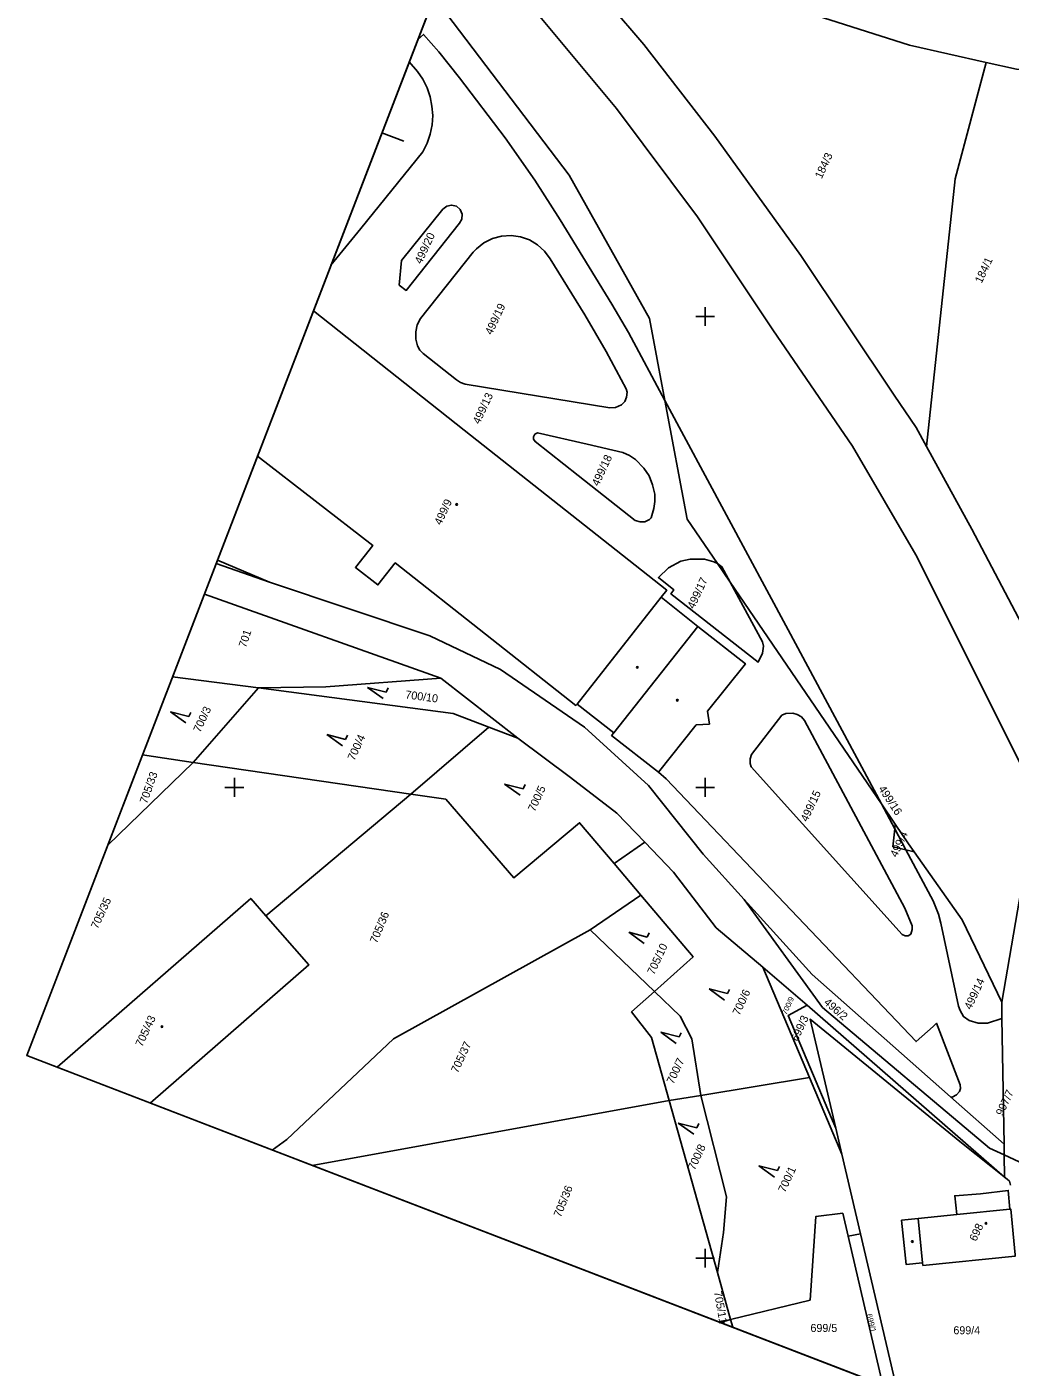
# Model space of a CAD drawing. Extents: x -755344 to -754412, y -1162670 to -1161477.
# Drawn here: x -755344.1 to -755135.2, y -1162523.1 to -1162238.5 of the extents above; entities that cross this region are included whole.
import ezdxf

# ---------------------------------------------------------------- set-up
doc = ezdxf.new("R2010")
doc.units = 0
for name, color, linetype in [('Formát', 7, 'Continuous'), ('Síť', 7, 'Continuous'), ('Vrstva 55', 7, 'Continuous'), ('Vrstva 56', 7, 'Continuous'), ('Vrstva 57', 7, 'Continuous'), ('Vrstva 58', 7, 'Continuous'), ('Vrstva 59', 7, 'Continuous')]:
    doc.layers.add(name, color=color, linetype=linetype)

msp = doc.modelspace()

# ---------------------------------------------------------------- linework, layer by layer
at = {"layer": 'Formát'}
for p, q in [((-755042.37, -1161673.02), (-755344.08, -1162456.97)), ((-755042.37, -1161673.02), (-755344.08, -1162456.97)), ((-755268.65, -1162260.99), (-755263.98, -1162262.78)), ((-755344.08, -1162456.97), (-754789.71, -1162670.32))]:
    msp.add_line(p, q, dxfattribs=at)
msp.add_lwpolyline([(-754488.01, -1161886.37), (-754789.71, -1162670.32), (-755344.08, -1162456.97), (-755042.37, -1161673.02)], close=True, dxfattribs=at)
for points in [[(-755344.08, -1162456.97), (-754789.71, -1162670.32), (-754488.01, -1161886.37), (-755042.37, -1161673.02)], [(-755344.08, -1162456.97), (-754789.71, -1162670.32), (-754488.01, -1161886.37), (-755042.37, -1161673.02)], [(-754789.71, -1162670.32), (-754488.01, -1161886.37), (-755042.37, -1161673.02), (-755344.08, -1162456.97)]]:
    msp.add_lwpolyline(points, dxfattribs=at)
at = {"layer": 'Síť'}
for points in [[(-755198, -1162300), (-755200, -1162300), (-755202, -1162300)], [(-755200, -1162298), (-755200, -1162300), (-755200, -1162302)], [(-755298, -1162400), (-755300, -1162400), (-755302, -1162400)], [(-755300, -1162398), (-755300, -1162400), (-755300, -1162402)], [(-755198, -1162400), (-755200, -1162400), (-755202, -1162400)], [(-755200, -1162398), (-755200, -1162400), (-755200, -1162402)], [(-755200, -1162498), (-755200, -1162500), (-755200, -1162502)], [(-755198, -1162500), (-755200, -1162500), (-755202, -1162500)]]:
    msp.add_lwpolyline(points, dxfattribs=at)
at = {"layer": 'Vrstva 55'}
for p, q in [((-755197.4, -1162352.43), (-755194.7, -1162356.4)), ((-755194.7, -1162356.4), (-755162.59, -1162403.5)), ((-755256.17, -1162376.79), (-755306.36, -1162358.97)), ((-755256.17, -1162376.79), (-755306.36, -1162358.97)), ((-755256.17, -1162376.79), (-755280.56, -1162378.65)), ((-755239.79, -1162389.54), (-755256.17, -1162376.79)), ((-755239.79, -1162389.54), (-755256.17, -1162376.79)), ((-755308.72, -1162394.69), (-755294.89, -1162378.88)), ((-755280.56, -1162378.65), (-755294.89, -1162378.88)), ((-755262.5, -1162401.42), (-755245.93, -1162387.2)), ((-755239.79, -1162389.54), (-755245.93, -1162387.2)), ((-755228.6, -1162397.87), (-755239.79, -1162389.54)), ((-755228.6, -1162397.87), (-755239.79, -1162389.54)), ((-755319.5, -1162393.12), (-755308.72, -1162394.69)), ((-755326.86, -1162412.25), (-755308.72, -1162394.69)), ((-755308.72, -1162394.69), (-755262.5, -1162401.42)), ((-755293.31, -1162427.26), (-755262.5, -1162401.42)), ((-755262.5, -1162401.42), (-755255.05, -1162402.51)), ((-755162.59, -1162403.5), (-755159.64, -1162407.83)), ((-755159.74, -1162408.83), (-755162.59, -1162403.5)), ((-755159.64, -1162407.83), (-755159.74, -1162408.83)), ((-755219.35, -1162416.19), (-755212.85, -1162411.61)), ((-755157.36, -1162413.27), (-755155.59, -1162413.71)), ((-755219.35, -1162416.19), (-755213.66, -1162422.91)), ((-755137.03, -1162445.6), (-755132.49, -1162419.21)), ((-755213.66, -1162422.91), (-755224.46, -1162430.27)), ((-755224.46, -1162430.27), (-755210.79, -1162443.34)), ((-755178.31, -1162446.22), (-755187.75, -1162438.21)), ((-755177.87, -1162461.62), (-755187.75, -1162438.21)), ((-755178.31, -1162446.22), (-755187.75, -1162438.21)), ((-755136.97, -1162449.09), (-755137.03, -1162445.6)), ((-755136.42, -1162482.75), (-755178.31, -1162446.22)), ((-755136.42, -1162482.75), (-755178.31, -1162446.22)), ((-755136.53, -1162475.81), (-755136.97, -1162449.09)), ((-755211.4, -1162453.1), (-755207.64, -1162466.53)), ((-755177.87, -1162461.62), (-755200.95, -1162465.43)), ((-755170.99, -1162477.93), (-755177.87, -1162461.62)), ((-755207.64, -1162466.53), (-755200.95, -1162465.43)), ((-755207.64, -1162466.53), (-755283.5, -1162480.29)), ((-755207.64, -1162466.53), (-755197.41, -1162503.06)), ((-755147.93, -1162465.72), (-755136.53, -1162475.81)), ((-755172.28, -1162472.41), (-755170.99, -1162477.93)), ((-755136.53, -1162475.81), (-755136.49, -1162478.06)), ((-755170.99, -1162477.93), (-755167.04, -1162494.84)), ((-755136.49, -1162478.06), (-755132.28, -1162480)), ((-755136.42, -1162482.75), (-755136.49, -1162478.06)), ((-755135.89, -1162483.24), (-755136.42, -1162482.75)), ((-755135.89, -1162483.24), (-755136.42, -1162482.75)), ((-755169.63, -1162495.32), (-755170.76, -1162490.41)), ((-755167.04, -1162494.84), (-755169.63, -1162495.32)), ((-755169.63, -1162495.32), (-755162.24, -1162526.95)), ((-755197.41, -1162503.06), (-755194.62, -1162513.04)), ((-755196.07, -1162513.44), (-755196.82, -1162513.65)), ((-755194.62, -1162513.04), (-755196.07, -1162513.44)), ((-755194.16, -1162514.67), (-755194.62, -1162513.04))]:
    msp.add_line(p, q, dxfattribs=at)
for points in [[(-755251.78, -1162217.14), (-755236.92, -1162234.12), (-755218.86, -1162255.78), (-755201.65, -1162278.82), (-755185.6, -1162302.84), (-755168.69, -1162327.53), (-755155.26, -1162350.62), (-755154.66, -1162351.82), (-755141.68, -1162377.77), (-755128.84, -1162403.34)], [(-755224.59, -1162220.51), (-755227.6, -1162225.16), (-755213.03, -1162242.21), (-755197.95, -1162261.69), (-755179.66, -1162287.01), (-755159.89, -1162316.68), (-755155.21, -1162323.55), (-755152.98, -1162327.62)], [(-755140.31, -1162246.01), (-755156.59, -1162242.36), (-755179.53, -1162235.08), (-755202.91, -1162226.05)], [(-755257.56, -1162232.16), (-755228.92, -1162270), (-755211.8, -1162300.42), (-755208.54, -1162317.82)], [(-755261.01, -1162241.13), (-755259.86, -1162240.09), (-755256.55, -1162243.81), (-755252.15, -1162249.27), (-755242.47, -1162262.02), (-755236.16, -1162271.02), (-755230.79, -1162279.46), (-755219.8, -1162297.35), (-755216.28, -1162303.42), (-755208.54, -1162317.82)], [(-755279.48, -1162289.12), (-755273.15, -1162281.3), (-755259.96, -1162264.99), (-755259.05, -1162263.18), (-755258.42, -1162261.28), (-755258.01, -1162259.3), (-755257.86, -1162257.3), (-755258.04, -1162255.29), (-755258.42, -1162253.32), (-755259.06, -1162251.4), (-755259.94, -1162249.61), (-755261.07, -1162247.95), (-755262.85, -1162245.91)], [(-755140.31, -1162246.01), (-755146.94, -1162270.72), (-755152.98, -1162327.62)], [(-755110.99, -1162250.12), (-755133.9, -1162247.44), (-755140.31, -1162246.01)], [(-755264.53, -1162288.11), (-755255.71, -1162277.19), (-755254.89, -1162276.55), (-755253.87, -1162276.34), (-755252.85, -1162276.59), (-755252.05, -1162277.27), (-755251.62, -1162278.23), (-755251.7, -1162279.29), (-755252.21, -1162280.19), (-755263.5, -1162294.45), (-755265.01, -1162293.32), (-755264.53, -1162288.11)], [(-755249.26, -1162286.35), (-755248.56, -1162285.61), (-755246.99, -1162284.35), (-755245.19, -1162283.44), (-755243.24, -1162282.9), (-755241.22, -1162282.77), (-755239.23, -1162283.04), (-755237.32, -1162283.7), (-755235.58, -1162284.76), (-755234.1, -1162286.1), (-755232.92, -1162287.74), (-755225.57, -1162299.65), (-755221.06, -1162307.45), (-755216.79, -1162315.38), (-755216.6, -1162316.07), (-755216.69, -1162317.09), (-755217.09, -1162318.02), (-755217.77, -1162318.78), (-755219.05, -1162319.34), (-755220.22, -1162319.37), (-755250.99, -1162314.33), (-755251.97, -1162314.01), (-755252.8, -1162313.43), (-755259.87, -1162307.84), (-755260.58, -1162307.15), (-755261.1, -1162306.25), (-755261.47, -1162304.77), (-755261.48, -1162303.26), (-755261.16, -1162301.78), (-755260.47, -1162300.43), (-755249.26, -1162286.35)], [(-755209.95, -1162396.8), (-755201.89, -1162386.73), (-755199.09, -1162386.57), (-755199.54, -1162383.8), (-755191.47, -1162373.73), (-755201.54, -1162365.82), (-755209.34, -1162359.63), (-755208.16, -1162358.13), (-755251.18, -1162324.13), (-755283.21, -1162298.82)], [(-755208.54, -1162317.82), (-755203.83, -1162343), (-755197.4, -1162352.43)], [(-755235.64, -1162324.73), (-755225.07, -1162327.13), (-755217.5, -1162328.85), (-755216.09, -1162329.51), (-755214.81, -1162330.37), (-755213.06, -1162332.17), (-755211.93, -1162333.85), (-755211.16, -1162335.75), (-755210.72, -1162337.72), (-755210.71, -1162339.28), (-755210.94, -1162340.77), (-755211.5, -1162342.72), (-755211.86, -1162343.11), (-755212.81, -1162343.61), (-755213.83, -1162343.62), (-755214.89, -1162343.31), (-755226.97, -1162333.77), (-755236.12, -1162326.55), (-755236.44, -1162326.06), (-755236.45, -1162325.52), (-755236.16, -1162325.01), (-755235.64, -1162324.73)], [(-755152.98, -1162327.62), (-755143.37, -1162345.14), (-755132.01, -1162366.71), (-755123.39, -1162386.22)], [(-755209.95, -1162396.8), (-755219.88, -1162388.97), (-755219.41, -1162388.42), (-755227.22, -1162382.29), (-755227.45, -1162382.59), (-755265.84, -1162352.32), (-755269.5, -1162357.01), (-755274.29, -1162353.28), (-755270.6, -1162348.62), (-755295.07, -1162329.63)], [(-755303.57, -1162351.72), (-755292.52, -1162356.43)], [(-755194.7, -1162356.4), (-755187.86, -1162369.11), (-755187.6, -1162370.02), (-755187.8, -1162371.5), (-755188.78, -1162373.43), (-755207.28, -1162358.88), (-755206.63, -1162358.07), (-755209.93, -1162355.45), (-755207.82, -1162353.4), (-755205.14, -1162351.97), (-755203.16, -1162351.5), (-755200.13, -1162351.55), (-755198.17, -1162352.07), (-755197.4, -1162352.43)], [(-755292.52, -1162356.43), (-755303.85, -1162352.45)], [(-755292.52, -1162356.43), (-755258.5, -1162367.8), (-755243.5, -1162374.93), (-755225.6, -1162387.24), (-755212.01, -1162399.57), (-755200.43, -1162414.21), (-755191.72, -1162423.82)], [(-755294.89, -1162378.88), (-755313.1, -1162376.49)], [(-755245.93, -1162387.2), (-755253.53, -1162384.31), (-755294.89, -1162378.88)], [(-755190.23, -1162395.62), (-755190.43, -1162394.96), (-755190.46, -1162393.97), (-755190.17, -1162393.03), (-755183.69, -1162384.68), (-755182.85, -1162384.3), (-755181.4, -1162384.23), (-755180.44, -1162384.49), (-755179.57, -1162384.99), (-755178.91, -1162385.78), (-755157.62, -1162425.68), (-755156.05, -1162429.38), (-755156.03, -1162430.21), (-755156.34, -1162431.15), (-755156.88, -1162431.52), (-755157.56, -1162431.53), (-755158.19, -1162431.25), (-755190.23, -1162395.62)], [(-755147.93, -1162465.72), (-755147.53, -1162465.77), (-755146.63, -1162465.33), (-755146.01, -1162464.59), (-755145.78, -1162463.97), (-755145.86, -1162463.15), (-755150.88, -1162450.09), (-755151.6, -1162450.76), (-755155.2, -1162454), (-755208.3, -1162398.17), (-755209.95, -1162396.8)], [(-755212.85, -1162411.61), (-755218.77, -1162405.46), (-755228.6, -1162397.87)], [(-755212.85, -1162411.61), (-755218.77, -1162405.46), (-755228.6, -1162397.87)], [(-755255.05, -1162402.51), (-755240.65, -1162419.2), (-755226.69, -1162407.51), (-755219.35, -1162416.19)], [(-755159.64, -1162407.83), (-755156.82, -1162411.96), (-755155.59, -1162413.71)], [(-755159.74, -1162408.83), (-755160.13, -1162412.59), (-755157.36, -1162413.27)], [(-755187.75, -1162438.21), (-755197.66, -1162429.8), (-755206.7, -1162418), (-755212.85, -1162411.61)], [(-755187.75, -1162438.21), (-755197.66, -1162429.8), (-755206.7, -1162418), (-755212.85, -1162411.61)], [(-755136.97, -1162449.09), (-755140.07, -1162450.08), (-755142.03, -1162450.09), (-755143.92, -1162449.51), (-755145.15, -1162448.68), (-755145.88, -1162447.38), (-755146.21, -1162446.45), (-755149.93, -1162428.84), (-755150.43, -1162426.9), (-755151.56, -1162424.12), (-755157.36, -1162413.27)], [(-755155.59, -1162413.71), (-755145.43, -1162428.12), (-755137.03, -1162445.6)], [(-755210.79, -1162443.34), (-755202.59, -1162436), (-755213.66, -1162422.91)], [(-755337.66, -1162459.44), (-755296.53, -1162423.57), (-755293.31, -1162427.26)], [(-755191.72, -1162423.82), (-755177.29, -1162439.75), (-755147.93, -1162465.72)], [(-755136.49, -1162478.06), (-755139.64, -1162476.61), (-755175.06, -1162446.75), (-755191.72, -1162423.82)], [(-755293.31, -1162427.26), (-755284.2, -1162437.71), (-755317.87, -1162467.06)], [(-755291.95, -1162477.03), (-755288.84, -1162474.8), (-755266.17, -1162453.41), (-755224.46, -1162430.27)], [(-755210.79, -1162443.34), (-755215.65, -1162447.7), (-755211.4, -1162453.1)], [(-755210.79, -1162443.34), (-755205.32, -1162448.57), (-755202.86, -1162453.37), (-755200.95, -1162465.43)], [(-755178.31, -1162446.22), (-755182.38, -1162448.48), (-755173.18, -1162470.28), (-755172.28, -1162472.41)], [(-755172.28, -1162472.41), (-755177.72, -1162449.23), (-755145.9, -1162475.22), (-755135.89, -1162483.24)], [(-755200.95, -1162465.43), (-755195.47, -1162486.94), (-755196.12, -1162494.51), (-755197.41, -1162503.06)], [(-755135.17, -1162484.49), (-755135.35, -1162483.65), (-755135.89, -1162483.24)], [(-755135.17, -1162484.49), (-755135.35, -1162483.65), (-755135.89, -1162483.24)], [(-755135.28, -1162489.58), (-755135.65, -1162485.61), (-755141.54, -1162486.3), (-755146.99, -1162486.73), (-755146.57, -1162490.74), (-755154.79, -1162491.58), (-755158.29, -1162491.94), (-755157.33, -1162501.33), (-755153.82, -1162500.97), (-755153.76, -1162501.54), (-755134.18, -1162499.57), (-755134.2, -1162499.29), (-755135.1, -1162489.56), (-755135.28, -1162489.58)], [(-755170.76, -1162490.41), (-755176.47, -1162491.13), (-755177.73, -1162508.9), (-755194.62, -1162513.04)], [(-755159.22, -1162528.11), (-755167.04, -1162494.84)], [(-755196.07, -1162513.44), (-755196.02, -1162513.95)]]:
    msp.add_lwpolyline(points, dxfattribs=at)
at = {"layer": 'Vrstva 56'}
for p, q in [((-755209.34, -1162359.63), (-755227.22, -1162382.29)), ((-755219.41, -1162388.42), (-755201.54, -1162365.82)), ((-755159.74, -1162408.83), (-755157.36, -1162413.27)), ((-755146.57, -1162490.74), (-755135.28, -1162489.58)), ((-755154.79, -1162491.58), (-755153.82, -1162500.97))]:
    msp.add_line(p, q, dxfattribs=at)
for points in [[(-755208.54, -1162317.82), (-755182.37, -1162366.53), (-755162.59, -1162403.5)], [(-755197.4, -1162352.43), (-755196.45, -1162353.14), (-755194.7, -1162356.4)]]:
    msp.add_lwpolyline(points, dxfattribs=at)
at = {"layer": 'Vrstva 58'}
for p, q in [((-755267.76, -1162379.78), (-755271.71, -1162378.77)), ((-755271.71, -1162378.77), (-755268.4, -1162381.14)), ((-755267.76, -1162379.78), (-755267.34, -1162378.88)), ((-755309.64, -1162384.96), (-755313.58, -1162383.95)), ((-755313.58, -1162383.95), (-755310.27, -1162386.32)), ((-755309.64, -1162384.96), (-755309.22, -1162384.06)), ((-755276.41, -1162389.8), (-755280.36, -1162388.79)), ((-755280.36, -1162388.79), (-755277.05, -1162391.16)), ((-755276.41, -1162389.8), (-755275.99, -1162388.9)), ((-755238.65, -1162400.32), (-755242.6, -1162399.31)), ((-755242.6, -1162399.31), (-755239.29, -1162401.68)), ((-755238.65, -1162400.32), (-755238.23, -1162399.42)), ((-755212.29, -1162431.79), (-755216.24, -1162430.78)), ((-755216.24, -1162430.78), (-755212.93, -1162433.15)), ((-755212.29, -1162431.79), (-755211.87, -1162430.89)), ((-755195.23, -1162443.8), (-755199.18, -1162442.79)), ((-755199.18, -1162442.79), (-755195.87, -1162445.16)), ((-755195.23, -1162443.8), (-755194.81, -1162442.9)), ((-755205.5, -1162453.01), (-755209.45, -1162452)), ((-755209.45, -1162452), (-755206.14, -1162454.37)), ((-755205.5, -1162453.01), (-755205.08, -1162452.11)), ((-755201.8, -1162472.29), (-755205.75, -1162471.28)), ((-755205.75, -1162471.28), (-755202.44, -1162473.65)), ((-755201.8, -1162472.29), (-755201.38, -1162471.39)), ((-755184.66, -1162481.39), (-755188.61, -1162480.38)), ((-755188.61, -1162480.38), (-755185.3, -1162482.75)), ((-755184.66, -1162481.39), (-755184.24, -1162480.49))]:
    msp.add_line(p, q, dxfattribs=at)
at = {"layer": 'Vrstva 59'}
for centre in [(-755252.79, -1162339.91), (-755214.42, -1162374.51), (-755205.91, -1162381.48), (-755315.36, -1162450.82), (-755140.37, -1162492.58), (-755156.02, -1162496.46)]:
    msp.add_circle(centre, 0.175, dxfattribs=at)

# ---------------------------------------------------------------- texts
at = {"layer": 'Vrstva 57'}
for s, height, rotation, p in [('184/3', 1.7, 65, (-755175.27, -1162270.86)), ('499/20', 1.7, 65, (-755260.27, -1162288.97)), ('184/1', 1.7, 65, (-755141.29, -1162293.07)), ('499/19', 1.7, 65, (-755245.31, -1162304.02)), ('499/13', 1.7, 65, (-755247.93, -1162322.99)), ('499/18', 1.7, 65, (-755222.65, -1162336.15)), ('499/9', 1.7, 65, (-755256.1, -1162344.43)), ('499/17', 1.7, 65, (-755202.36, -1162362.22)), ('701', 1.7, 71.5779, (-755297.54, -1162370.44)), ('700/10', 1.7, 352.4757, (-755263.76, -1162381.08)), ('700/3', 1.7, 65, (-755307.27, -1162388.47)), ('700/4', 1.7, 65, (-755274.52, -1162394.45)), ('705/33', 1.7, 70.511, (-755318.57, -1162403.6)), ('700/5', 1.7, 65, (-755236.21, -1162405.29)), ('499/16', 1.7, 303.3494, (-755163.29, -1162400.3)), ('499/15', 1.7, 65, (-755178.31, -1162407.43)), ('499/4', 1.7, 65, (-755159.3, -1162414.99)), ('705/35', 1.7, 65, (-755329.02, -1162430.19)), ('705/36', 1.7, 67.4349, (-755269.73, -1162433.25)), ('705/10', 1.7, 65, (-755210.87, -1162439.94)), ('499/14', 1.7, 65, (-755143.54, -1162447.33)), ('700/6', 1.7, 65, (-755192.75, -1162448.56)), ('700/9', 1.139, 65, (-755182.75, -1162448.38)), ('496/2', 1.7, 318.8413, (-755174.94, -1162445.87)), ('705/43', 1.7, 65, (-755319.57, -1162455.24)), ('699/3', 1.7, 65, (-755180.37, -1162454.09)), ('705/37', 1.7, 65, (-755252.55, -1162460.8)), ('700/7', 1.7, 65, (-755206.76, -1162463.15)), ('997/7', 1.7, 65, (-755136.83, -1162469.89)), ('700/8', 1.7, 65, (-755202.23, -1162481.44)), ('700/1', 1.7, 65, (-755183.05, -1162486.18)), ('705/36', 1.7, 68.074, (-755230.69, -1162491.43)), ('698', 1.7, 65, (-755142.46, -1162496.55)), ('705/11', 1.7, 280, (-755198.16, -1162507.15)), ('699/1', 1.2, 284, (-755165.77, -1162511.96))]:
    msp.add_text(s, height=height, rotation=rotation, dxfattribs=at).set_placement(p)
for s, p in [('699/5', (-755177.64, -1162515.66)), ('699/4', (-755147.29, -1162516.15))]:
    msp.add_text(s, height=1.7, dxfattribs=at).set_placement(p)

doc.saveas('drawing.dxf')
